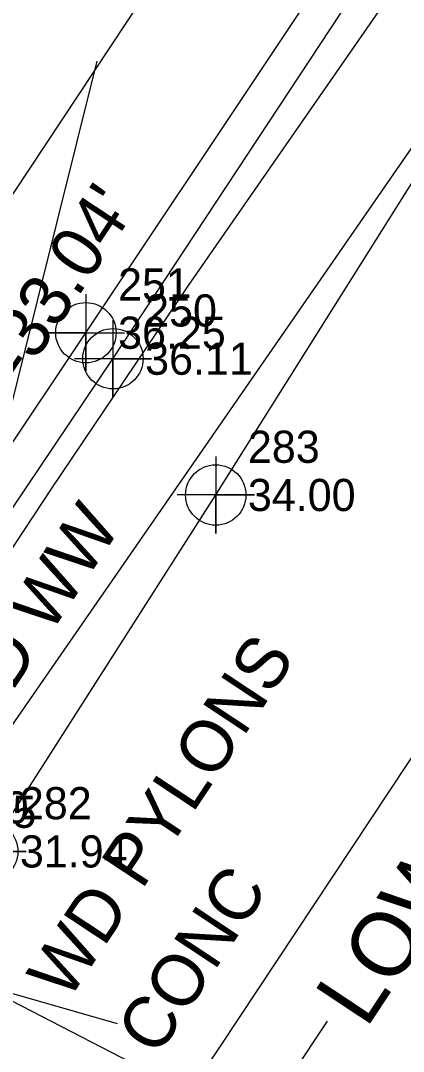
# Model space of a CAD drawing. Extents: x 2603627 to 2605187, y 896619 to 899063.
# Drawn here: x 2604593 to 2604622.7, y 898167.5 to 898247.7 of the extents above; entities that cross this region are included whole.
import ezdxf

# ---------------------------------------------------------------- set-up
doc = ezdxf.new("R2010")
doc.units = 0
for name, color, linetype in [('Default Symbol Leader', 7, 'Continuous'), ('Default Symbol Text', 7, 'Continuous'), ('Exist Guardrail', 7, 'Continuous'), ('Exist Horizontal Alignment', 7, 'Continuous'), ('Exist Horizontal Baseline Alignment', 7, 'Continuous'), ('Exist Hydro Stream or Body of Water', 7, 'Continuous'), ('Exist Other Culture Located Object Text', 7, 'Continuous'), ('Exist Property Tie Line', 7, 'Continuous'), ('Exist Right of Way Line', 7, 'Continuous'), ('Exist Roads EOP', 7, 'Continuous'), ('Exist Roads EOP Cogo Elevation', 7, 'Continuous'), ('Exist Roads EOP Cogo Number', 7, 'Continuous'), ('Exist Roads EOP Cogo Point CELL', 7, 'Continuous'), ('Exist Roads EOT', 7, 'Continuous'), ('Exist Roads EOT Cogo Elevation', 7, 'Continuous'), ('Exist Roads EOT Cogo Number', 7, 'Continuous'), ('Exist Roads EOT Cogo Point CELL', 7, 'Continuous'), ('Exist Structure Major Bridge Seat Top Elevation', 7, 'Continuous'), ('Exist Structure Major Bridge WW Cogo Elevation', 7, 'Continuous'), ('Exist Structure Major Bridge WW Leader', 7, 'Continuous'), ('Exist Structure Major Bridge WW Text', 7, 'Continuous'), ('Exist Utilities Water UG Line SUE LOS B', 7, 'Continuous'), ('Exist Utilities Water UG Line SUE LOS B Cogo Elevation', 7, 'Continuous'), ('Exist Utilities Water UG Line SUE LOS B Cogo Number', 7, 'Continuous'), ('Exist Utilities Water UG Line SUE LOS B Cogo Point CELL', 7, 'Continuous')]:
    doc.layers.add(name, color=color, linetype=linetype)

# ---------------------------------------------------------------- blocks, each defined once
blk = doc.blocks.new('EXIST ROADS EOP COGO POINT')
at = {"layer": 'Exist Roads EOP Cogo Point CELL'}
blk.add_lwpolyline([(0, 0.06), (0, -0.06), (0, 0), (0.06, 0), (-0.06, 0)], dxfattribs=at)
blk.add_circle((0, 0), 0.0469, dxfattribs=at)
blk = doc.blocks.new('EXIST ROADS EOT COGO POINT')
at = {"layer": 'Exist Roads EOT Cogo Point CELL'}
blk.add_lwpolyline([(0, 0.06), (0, -0.06), (0, 0), (-0.06, 0), (0.06, 0)], dxfattribs=at)
blk.add_circle((0, 0), 0.0469, dxfattribs=at)
blk = doc.blocks.new('EXIST UTILITIES WATER UG LINE SUE LOS B COGO POINT')
at = {"layer": 'Exist Utilities Water UG Line SUE LOS B Cogo Point CELL'}
blk.add_lwpolyline([(0, 0.06), (0, -0.06), (0, 0), (0.06, 0), (-0.06, 0)], dxfattribs=at)
blk.add_circle((0, 0), 0.0469, dxfattribs=at)

msp = doc.modelspace()

# ---------------------------------------------------------------- linework, layer by layer
at = {"layer": 'Default Symbol Leader'}
msp.add_line((2604608.764, 898157.759), (2604616.82, 898169.887), dxfattribs=at)
at = {"layer": 'Exist Guardrail'}
msp.add_lwpolyline([(2604631.981, 898264.559), (2604605.99, 898227.058), (2604595.344, 898211.259), (2604574.882, 898180.207)], dxfattribs=at)
at = {"layer": 'Exist Horizontal Alignment'}
msp.add_line((2604537.349, 898151.011), (2604647.762, 898317.915), dxfattribs=at)
at = {"layer": 'Exist Horizontal Baseline Alignment'}
msp.add_line((2604544.961, 898124.436), (2604793.601, 898483.903), dxfattribs=at)
at = {"layer": 'Exist Hydro Stream or Body of Water'}
msp.add_lwpolyline([(2604579.029, 898178.3), (2604601.562, 898166.672)], dxfattribs=at)
at = {"layer": 'Exist Property Tie Line'}
msp.add_line((2604598.893, 898244.519), (2604562.447, 898098.35), dxfattribs=at)
at = {"layer": 'Exist Right of Way Line'}
msp.add_line((2604579.05, 898123.424), (2604689.463, 898290.329), dxfattribs=at)
at = {"layer": 'Exist Roads EOP'}
for p, q in [((2604600.141, 898221.379), (2604629.439, 898265.837)), ((2604573.101, 898181.136), (2604600.141, 898221.379))]:
    msp.add_line(p, q, dxfattribs=at)
at = {"layer": 'Exist Roads EOT'}
msp.add_line((2604570.83, 898182.648), (2604598.038, 898223.4), dxfattribs=at)
msp.add_lwpolyline([(2604598.038, 898223.4), (2604627.235, 898267.233), (2604654.638, 898308.575), (2604683.284, 898352.013), (2604711.268, 898394.145), (2604737.977, 898434.049), (2604766.043, 898475.935), (2604794.958, 898519.255), (2604821.606, 898559.824), (2604848.894, 898601.402), (2604876.121, 898642.728), (2604904.396, 898685.354), (2604932.334, 898727.234), (2604960.287, 898769.489), (2604987.32, 898810.189), (2605014.123, 898850.946), (2605043.077, 898894.886), (2605050.197, 898905.717)], dxfattribs=at)
at = {"layer": 'Exist Structure Major Bridge WW Leader'}
msp.add_line((2604576.936, 898176.409), (2604600.462, 898169.701), dxfattribs=at)
at = {"layer": 'Exist Utilities Water UG Line SUE LOS B'}
msp.add_lwpolyline([(2604590.411, 898183.072), (2604608.125, 898210.782), (2604631.329, 898247.72), (2604631.98, 898248.774), (2604637.931, 898260.896), (2604650.01, 898281.754), (2604670.128, 898312.662), (2604706.143, 898370.49), (2604744.202, 898428.792), (2604775.847, 898478.143), (2604817.618, 898541.222), (2604844.764, 898580.182), (2604876.202, 898627.221), (2604907.55, 898675.151), (2604931.687, 898711.473), (2604963.512, 898758.627), (2604991.084, 898800.904), (2605022.229, 898847.261), (2605044.126, 898880.129), (2605057.71, 898900.736)], dxfattribs=at)

# ---------------------------------------------------------------- block references
at = {"layer": 'Exist Roads EOP Cogo Point CELL', "xscale": 50, "yscale": 50}
msp.add_blockref('EXIST ROADS EOP COGO POINT', (2604600.141, 898221.379), dxfattribs=at)
at = {"layer": 'Exist Roads EOT Cogo Point CELL', "xscale": 50, "yscale": 50}
msp.add_blockref('EXIST ROADS EOT COGO POINT', (2604598.038, 898223.4), dxfattribs=at)
at = {"layer": 'Exist Utilities Water UG Line SUE LOS B Cogo Point CELL', "xscale": 50, "yscale": 50}
for p in [(2604608.125, 898210.782), (2604590.411, 898183.072)]:
    msp.add_blockref('EXIST UTILITIES WATER UG LINE SUE LOS B COGO POINT', p, dxfattribs=at)

# ---------------------------------------------------------------- texts
at = {"layer": 'Default Symbol Text'}
msp.add_text("LOW WIRE=57.54'", height=5, rotation=56.40943, dxfattribs=at).set_placement((2604619.809, 898169.23))
at = {"layer": 'Exist Other Culture Located Object Text'}
msp.add_text('WD PYLONS', height=4, rotation=56.47848, dxfattribs=at).set_placement((2604596.638, 898171.35))
at = {"layer": 'Exist Roads EOP Cogo Elevation'}
msp.add_text('36.11', height=2.5, dxfattribs=at).set_placement((2604602.641, 898220.129))
at = {"layer": 'Exist Roads EOP Cogo Number'}
msp.add_text('250', height=2.5, dxfattribs=at).set_placement((2604602.641, 898223.879))
at = {"layer": 'Exist Roads EOT Cogo Elevation'}
msp.add_text('36.25', height=2.5, dxfattribs=at).set_placement((2604600.538, 898222.15))
at = {"layer": 'Exist Roads EOT Cogo Number'}
msp.add_text('251', height=2.5, dxfattribs=at).set_placement((2604600.538, 898225.9))
at = {"layer": 'Exist Structure Major Bridge Seat Top Elevation'}
msp.add_text("BRIDGE SEAT=33.04'", height=4, rotation=56.40944, dxfattribs=at).set_placement((2604572.449, 898188.544))
at = {"layer": 'Exist Structure Major Bridge WW Cogo Elevation'}
for s, p in [('35.40', (2604585.222, 898185.243)), ('35.45', (2604585.823, 898184.901))]:
    msp.add_text(s, height=2.5, dxfattribs=at).set_placement(p)
at = {"layer": 'Exist Structure Major Bridge WW Text'}
for s, p in [('WD WW', (2604589.503, 898191.219)), ('CONC', (2604603.574, 898167.014))]:
    msp.add_text(s, height=4, rotation=56.47848, dxfattribs=at).set_placement(p)
at = {"layer": 'Exist Utilities Water UG Line SUE LOS B Cogo Elevation'}
for s, p in [('34.00', (2604610.625, 898209.532)), ('31.94', (2604592.911, 898181.823))]:
    msp.add_text(s, height=2.5, dxfattribs=at).set_placement(p)
at = {"layer": 'Exist Utilities Water UG Line SUE LOS B Cogo Number'}
for s, p in [('283', (2604610.625, 898213.282)), ('282', (2604592.911, 898185.573))]:
    msp.add_text(s, height=2.5, dxfattribs=at).set_placement(p)

doc.saveas('drawing.dxf')
